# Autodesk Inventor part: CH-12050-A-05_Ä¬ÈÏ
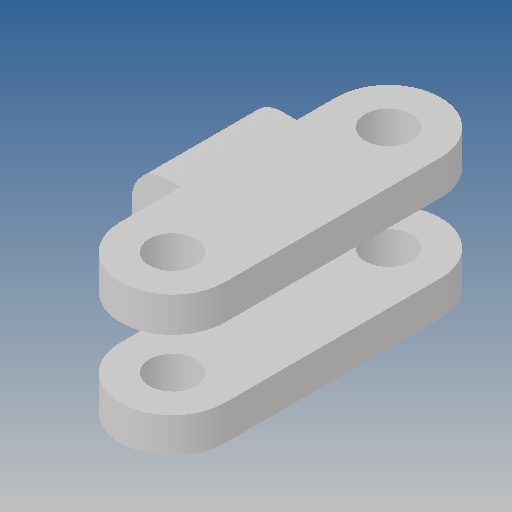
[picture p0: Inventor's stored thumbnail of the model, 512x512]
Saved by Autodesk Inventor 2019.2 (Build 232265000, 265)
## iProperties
Created: 2010-06
Part Number: CH-12050-A-05_Ä¬ÈÏ
Material: Ogólny
Document SubType Name: Modeling
Designer: CADENGINEERING4
Density: 1 g/cm^3
Appearance: Domyślna
Author: CADENGINEERING4
Revision Number: ÈÎºÎ
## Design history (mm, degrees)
feature "NONE"
node "Bryła1"
